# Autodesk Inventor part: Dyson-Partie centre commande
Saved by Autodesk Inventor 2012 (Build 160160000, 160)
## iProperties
Created: 2012-11
Part Number: Dyson-Partie centre commande
Material: Default
Document SubType Name: Modeling
Designer: Administrateur
Density: 1 g/cm^3
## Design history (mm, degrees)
node "Dyson-Partie centre commande1"
node "Dyson-Partie centre commande"
node "Base1"
